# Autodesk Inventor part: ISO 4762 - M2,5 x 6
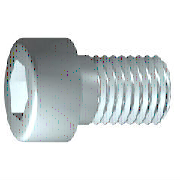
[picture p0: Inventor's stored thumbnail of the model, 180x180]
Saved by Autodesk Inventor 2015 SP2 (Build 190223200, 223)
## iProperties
IsCustomPart: 0
Created: 2012-02
Part Number: ISO 4762 - M2,5 x 6
Material: Edelstahl, 440C
Description: Innensechskantschraube
Document SubType Name: Modeling
Standard: ISO 4762
Designer: rmaryll
Standard Revision: Fourth edition 2004-03-01
Standards Organization: ISO
Language: de-DE
Size Designation: M2,5 x 6
Categories: <MemberInstance><Categories><Category DisplayName="Verbindungselemente" InternalName="e4da775c-781d-43d5-af7c-5136215cf5a6" Mnemonic="FSTN"><Category DisplayNam
Density: 7.75 g/cm^3
Appearance: Halbpoliert
Author: rmaryll
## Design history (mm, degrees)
sketch "Skizze1"
  geometry: L1 (-0.733, 0)-(6, 0); L2 (6, 0)-(6, 1.25); L3 (6, 1.25)-(1.125, 1.25); L4 (1.125, 1.25)-(0.849, 1.25); L5 (0.849, 1.25)-(0, 1.25); L6 (0, 1.25)-(0, 2.25); L7 (0, 2.25)-(-2.5, 2.25); L8 (-2.5, 2.25)-(-2.5, 1.155); L9 (-2.5, 1.155)-(-1.4, 1.155); L10 (-1.4, 1.155)-(-0.733, 0); L11 (-4.2, 0)-(7.7, 0) reference; L12 (0, -0.45)-(0, 2.7) reference; L13 (1.125, 1.25)-(0, 1.25)
  constraints: 22 end point, 6 parallel, 2 collinear, 2 perpendicular, 1 horizontal, 1 point on line
  dimensions: "d1" = 4.875 distance from line of L3.end L2 (= GEL); "d2" = 0.27615 distance of L4.end L3.end (computed from GAL); "d3" = 2.5 distance between parallel lines of L8 L6 (= KOH); "d4" = 1.1 distance of L8.end L9.end (= INTI); "d5" = 60 deg angle of L10 L1; "d6" = 2.5 diameter of L3 L1 (= GD); "d7" = 2.5 diameter of L5 L1 (= BDM); "d8" = 2.3094 diameter of L9 L1 (= 1.1547 x SW); "d9" = 4.5 diameter of L7 L1 (= KOD); "d26" = 6 distance between parallel lines of L12 L2 (= NLG)
revolve "Körper" sketch "Skizze1" stored, may be unused: angle "d10" = 90 deg
sketch "Skizze2"
  geometry: L1 (0, -3.15)-(0, 3.15) reference; L2 (-3.15, 0)-(3.15, 0) reference; L3 (1.155, 0)-(0.577, -1); L4 (0.577, -1)-(-0.577, -1); L5 (-0.577, -1)-(-1.155, 0); L6 (-1.155, 0)-(-0.577, 1); L7 (-0.577, 1)-(0.577, 1); L8 (0.577, 1)-(1.155, 0); 2 further points
  constraints: 12 end point, 1 coincident, 1 horizontal alignment, 1 point on line, 12 other
extrude "Loch" join sketch "Skizze2" stored distance "d11" = 10; taper "d12" = 0 deg
workplane "Work Plane1"
fillet "Fillet2" dims "d30" = 0.1 (= R)
body "Solid1"
fillet "Rundung1" dims "d17" = 0.25 (= RR)
feature "Gewinde" dims "d13" = 4.875 (= GEL), "d14" = 0
chamfer "Fase1" distance "d15" = 0.27605 (= -0.5 x SPD + 0.5 x GD); stored, may be unused: second distance "d16" = 0.27605 (= GUL), angle "d27" = 45 deg
other parameters: "GD" = 2.5 [user parameter; used in 2 equation terms], "NLG" = 6 [user parameter; used in 1 equation term], "GEL" = 4.875 [user parameter; used in 2 equation terms], "KOD" = 4.5 [user parameter; used in 1 equation term], "KOH" = 2.5 [user parameter; used in 1 equation term], "INTI" = 1.1 [user parameter; used in 1 equation term], "GAL" = 0.27605 (= 0.61345 x PTC) [user parameter; used in 1 equation term], "GUL" = 0.27605 (= 0.61345 x PTC) [user parameter; used in 1 equation term], "BDM" = 2.5 (= NND) [user parameter; used in 1 equation term], "SW" = 2 [user parameter; used in 2 equation terms], "RR" = 0.25 [user parameter; used in 1 equation term], "SPD" = 1.94789 (= NND - 1.2269 x PTC) [user parameter; used in 1 equation term], "d19" = 0, "d28" = 0, "d29" = 0, "R" = 0.1 [user parameter; used in 1 equation term], "TOA" = 30 deg [user parameter], "GD1" = 1.94789 (= THREADDIA - 1.2269 x PTC) [user parameter], "THREADDIA" = 2.5 [user parameter; used in 1 equation term], "FAWI" = 45 deg [user parameter], "TPU" = 22.22222 (computed from PTC) [user parameter], "PTC" = 0.45 [user parameter; used in 5 equation terms], "NND" = 2.5 [user parameter; used in 2 equation terms], "E0" = 2.31 (= 1.155 x SW) [user parameter]
